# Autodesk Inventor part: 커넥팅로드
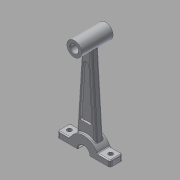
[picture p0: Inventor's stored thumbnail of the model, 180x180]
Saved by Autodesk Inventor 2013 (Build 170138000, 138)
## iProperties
Created: 2016-11
Part Number: 커넥팅로드
Material: 알루미늄 6061
Document SubType Name: Modeling
Designer: mduedu
Density: 2.71 g/cm^3
Mass: 44.5491 g
Surface Area: 86.7069 cm^2
Volume: 16.4388 cm^3
Author: mduedu
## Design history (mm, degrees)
sketch "스케치1" dims "d0" = 30, "d3" = 15
  geometry: L1 (0, 0)-(0, 96); L2 (-5, 90.41)-(-10, 11.18); L3 (5, 90.41)-(10, 11.18); C1 r 6 at (0, 0); C2 r 4 at (0, 96); 3 further points
  constraints: 6 end point, 4 coincident, 2 centre point, 2 symmetric about line, 1 vertical, 6 other
  dimensions: "d1" = 12 diameter of C1; "d2" = 8 diameter of C2; "d4" = 96 distance of L1.start L1.end; "d6" = 10 distance from line of L1 L2.end; "d7" = 5 distance from line of L1 L2.start
extrude "돌출1" new body sketch "스케치1" stored distance "d8" = 13; taper "d9" = 0 deg
extrude "돌출2" join sketch "스케치1" stored distance "d10" = 32; taper "d11" = 0 deg
sketch "스케치2"
  geometry: L1 (5, 90.41)-(10, 11.18) reference; L2 (-5, 90.41)-(-10, 11.18) reference; A1 r 7.5 centre (0, 96) between (5, 90.41) and (-5, 90.41) reference; A2 r 15 centre (0, 0) between (10, 11.18) and (-10, 11.18) reference
extrude "돌출3" join sketch "스케치2" stored distance "d12" = 8; taper "d13" = 0 deg
sketch "스케치3"
  geometry: L1 (-2.732, 78.715)-(-6.171, 24.226); L2 (2.732, 78.715)-(6.171, 24.226); L3 (0, 78.5)-(0, 25); A1 r 17.5 centre (0, 96) between (-2.732, 78.715) and (2.732, 78.715); A2 r 25 centre (0, 0) between (6.171, 24.226) and (-6.171, 24.226); 9 further points; 2 other entities
  constraints: 6 end point, 6 point on circle, 2 centre point, 1 symmetric about line, 1 vertical alignment, 6 other
  dimensions: "d18" = 10 dimension on A1; "d19" = 10 dimension on A2; "d20" = 3 dimension on L1
extrude "돌출4" cut sketch "스케치3" distance "d21" = 2; taper "d22" = 0 deg
fillet "모깎기1" dims "d23" = 2
fillet "모깎기2" dims "d24" = 2
fillet "모깎기3" dims "d25" = 1
chamfer "모따기1" distance "d26" = 0.5; stored, may be unused: second distance "d27" = 2, angle "d28" = 45 deg
sketch "스케치4"
  geometry: L1 (-27, -6)-(-13.748, -6); L2 (27, -6)-(27, 6); L3 (27, 6)-(13.748, 6); L4 (-27, 6)-(-27, -6); L5 (-27, -6)-(27, 6); L6 (27, -6)-(-27, 6); L7 (-13.748, 6)-(-27, 6); L8 (13.748, 6)-(-13.748, 6); L9 (13.748, -6)-(27, -6); L10 (-13.748, -6)-(13.748, -6); A1 r 15 centre (0, 0) between (-13.748, 6) and (13.748, 6) reference; 1 further point
  constraints: 20 end point, 10 parallel, 4 point on circle, 3 horizontal, 3 perpendicular, 2 midpoint
  dimensions: "d29" = 54 distance of L1.start L2.start; "d31" = 12 distance of L2.start L2.end
extrude "돌출5" join sketch "스케치4" stored distance "d32" = 0; taper "d33" = 0 deg
fillet "모깎기4" dims "d34" = 2
fillet "모깎기5" dims "d35" = 1
fillet "모깎기6" dims "d36" = 1
sketch "스케치5"
  geometry: L1 (1, 0)-(1, 9) reference; L2 (-18.5, 20.5)-(-33.5, 20.5) reference; L3 (-33.5, -11.5)-(-18.5, -11.5) reference; L4 (-26, 20.5)-(-26, -11.5); 3 further points
  constraints: 2 end point, 2 midpoint, 1 horizontal alignment, 1 symmetric about line
  dimensions: "d37" = 6 distance from line of point (-5, 4.5) L1
feature "분할1"
sketch "스케치7"
  geometry: 2 further points
  constraints: 2 other
hole "구멍2" sketch "스케치7" at (-47, 4.5), (-5, 4.5) diameter "d45" = 4.5; stored, may be unused: countersink angle "d49" = 90 deg, drill point angle "d51" = 0 deg; dims "d46" = 6, "d47" = 4, "d48" = 2, "d50" = 8
node "솔리드1"
mirror "대칭1"
other parameters: "d16" = 4, "d17" = 4
